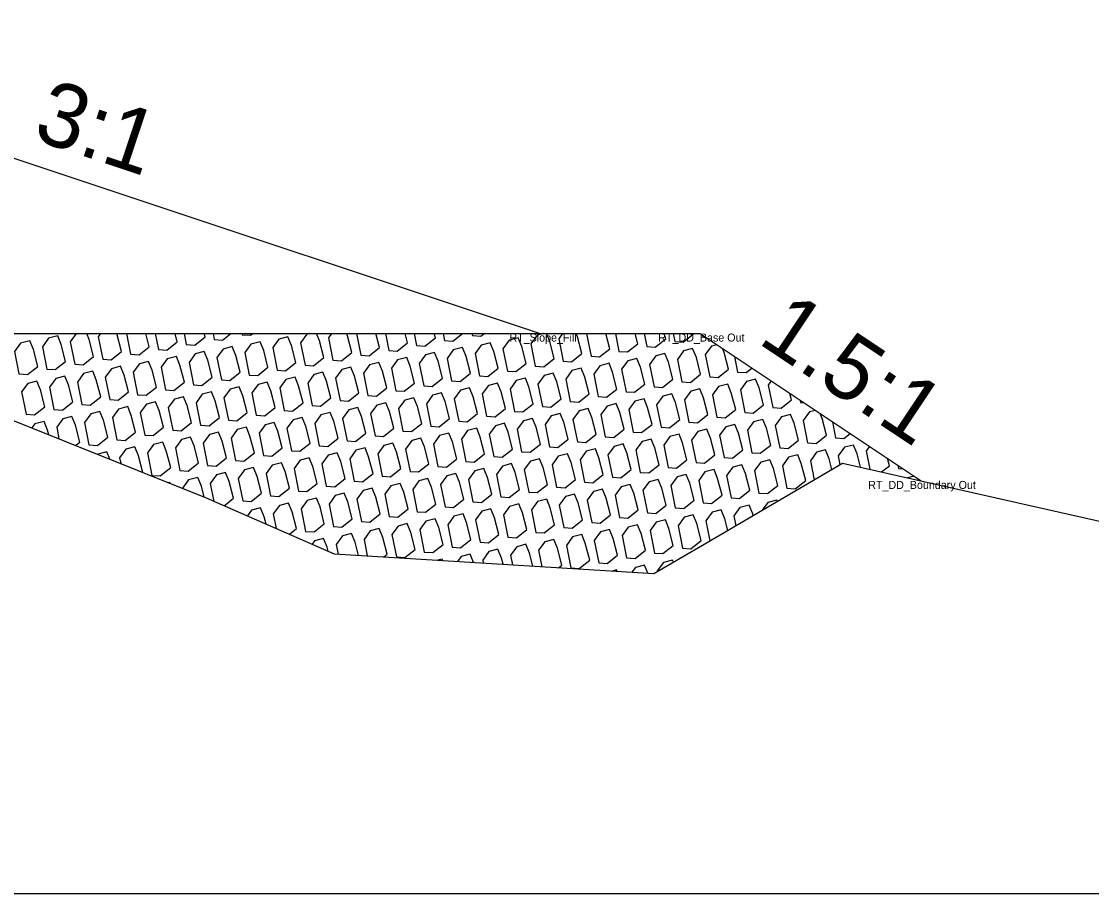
# Model space of a CAD drawing. Extents: x -26 to 203, y -10 to 20020.
# Drawn here: x 125.23 to 138.6, y 17000 to 17010.9 of the extents above; entities that cross this region are included whole.
import ezdxf

# ---------------------------------------------------------------- set-up
doc = ezdxf.new("R2010")
doc.units = 0
for name, color, linetype in [('Default', 7, 'Continuous'), ('Exist Cross Section Cell', 7, 'Continuous'), ('Exist XS Ground Line', 7, 'Continuous'), ('Old_Level_1', 7, 'Continuous'), ('Prop CMT Rip Rap Class II', 7, 'Continuous'), ('Prop CMT Slope Grass', 7, 'Continuous'), ('Prop XS Side Slope Text', 7, 'Continuous')]:
    doc.layers.add(name, color=color, linetype=linetype)

msp = doc.modelspace()

# ---------------------------------------------------------------- linework, layer by layer
at = {"layer": 'Exist Cross Section Cell'}
msp.add_line((100, 17000), (200, 17000), dxfattribs=at)
at = {"layer": 'Exist XS Ground Line'}
for p, q in [((124.169, 17006.298), (127.535, 17004.945)), ((133.788, 17004.385), (135.487, 17005.379)), ((135.487, 17005.379), (148.703, 17002.404)), ((127.535, 17004.945), (129.136, 17004.246)), ((133.13, 17004), (133.788, 17004.385)), ((129.136, 17004.246), (129.884, 17004.2)), ((129.884, 17004.2), (133.13, 17004))]:
    msp.add_line(p, q, dxfattribs=at)
at = {"layer": 'Old_Level_1'}
for p, q in [((126.538, 17007), (126.589, 17006.741)), ((126.899, 17007), (126.938, 17006.802)), ((127.259, 17007), (127.286, 17006.863)), ((127.62, 17007), (127.635, 17006.925)), ((127.981, 17007), (127.984, 17006.986)), ((129.413, 17007), (129.467, 17006.728)), ((129.774, 17007), (129.816, 17006.79)), ((130.135, 17007), (130.164, 17006.851)), ((130.495, 17007), (130.513, 17006.913)), ((130.856, 17007), (130.861, 17006.974)), ((132.649, 17007), (132.693, 17006.777)), ((133.01, 17007), (133.042, 17006.839)), ((133.371, 17007), (133.39, 17006.9)), ((133.735, 17006.981), (133.739, 17006.962)), ((133.739, 17006.962), (133.767, 17006.96)), ((134.138, 17006.712), (134.176, 17006.519)), ((134.957, 17006.166), (134.963, 17006.138)), ((134.963, 17006.138), (135.004, 17006.135)), ((135.36, 17005.898), (135.4, 17005.695)), ((136.179, 17005.352), (136.186, 17005.314)), ((136.186, 17005.314), (136.241, 17005.31)), ((136.379, 17005.218), (136.297, 17005.197)), ((136.435, 17005.166), (136.426, 17005.187))]:
    msp.add_line(p, q, dxfattribs=at)
for points in [[(125.543, 17006.556), (125.649, 17006.549), (125.778, 17006.652), (125.724, 17006.862), (125.679, 17006.972), (125.565, 17006.943), (125.488, 17006.836)], [(125.195, 17006.495), (125.3, 17006.487), (125.43, 17006.59), (125.375, 17006.801), (125.33, 17006.911), (125.216, 17006.881), (125.139, 17006.775)], [(133.131, 17006.335), (133.236, 17006.327), (133.365, 17006.43), (133.311, 17006.641), (133.266, 17006.751), (133.152, 17006.721), (133.075, 17006.615)], [(133.479, 17006.396), (133.585, 17006.389), (133.714, 17006.492), (133.66, 17006.702), (133.614, 17006.812), (133.501, 17006.783), (133.424, 17006.676)], [(129.207, 17006.163), (129.312, 17006.155), (129.442, 17006.258), (129.388, 17006.469), (129.342, 17006.579), (129.229, 17006.549), (129.152, 17006.443)], [(129.556, 17006.224), (129.661, 17006.217), (129.791, 17006.32), (129.736, 17006.53), (129.691, 17006.64), (129.577, 17006.611), (129.5, 17006.504)], [(132.433, 17006.212), (132.539, 17006.204), (132.668, 17006.307), (132.614, 17006.518), (132.569, 17006.628), (132.455, 17006.598), (132.378, 17006.492)], [(132.782, 17006.273), (132.887, 17006.266), (133.017, 17006.369), (132.962, 17006.579), (132.917, 17006.689), (132.804, 17006.66), (132.726, 17006.553)], [(128.51, 17006.04), (128.615, 17006.032), (128.745, 17006.135), (128.69, 17006.346), (128.645, 17006.456), (128.531, 17006.426), (128.454, 17006.32)], [(128.859, 17006.101), (128.964, 17006.094), (129.093, 17006.197), (129.039, 17006.407), (128.994, 17006.517), (128.88, 17006.488), (128.803, 17006.381)], [(132.085, 17006.15), (132.19, 17006.143), (132.32, 17006.246), (132.265, 17006.456), (132.22, 17006.566), (132.106, 17006.537), (132.029, 17006.43)], [(125.284, 17005.991), (125.389, 17005.983), (125.519, 17006.086), (125.464, 17006.297), (125.419, 17006.406), (125.305, 17006.377), (125.228, 17006.271)], [(127.813, 17005.917), (127.918, 17005.909), (128.048, 17006.012), (127.993, 17006.223), (127.948, 17006.333), (127.834, 17006.303), (127.757, 17006.197)], [(128.161, 17005.978), (128.267, 17005.971), (128.396, 17006.074), (128.342, 17006.284), (128.297, 17006.394), (128.183, 17006.365), (128.106, 17006.258)], [(130.69, 17005.904), (130.796, 17005.897), (130.925, 17006), (130.871, 17006.211), (130.826, 17006.32), (130.712, 17006.291), (130.635, 17006.184)], [(133.917, 17005.954), (134.022, 17005.946), (134.152, 17006.049), (134.097, 17006.26), (134.052, 17006.369), (133.938, 17006.34), (133.861, 17006.234)], [(127.116, 17005.794), (127.221, 17005.786), (127.35, 17005.889), (127.296, 17006.1), (127.251, 17006.21), (127.137, 17006.18), (127.06, 17006.074)], [(127.464, 17005.855), (127.57, 17005.848), (127.699, 17005.951), (127.645, 17006.161), (127.599, 17006.271), (127.486, 17006.242), (127.409, 17006.135)], [(130.342, 17005.843), (130.447, 17005.835), (130.577, 17005.939), (130.522, 17006.149), (130.477, 17006.259), (130.363, 17006.229), (130.286, 17006.123)], [(126.418, 17005.671), (126.524, 17005.663), (126.653, 17005.767), (126.599, 17005.977), (126.554, 17006.087), (126.44, 17006.057), (126.363, 17005.951)], [(126.767, 17005.732), (126.872, 17005.725), (127.002, 17005.828), (126.947, 17006.039), (126.902, 17006.148), (126.789, 17006.119), (126.711, 17006.012)], [(132.174, 17005.646), (132.279, 17005.639), (132.409, 17005.742), (132.354, 17005.952), (132.309, 17006.062), (132.195, 17006.033), (132.118, 17005.926)], [(128.599, 17005.536), (128.704, 17005.528), (128.834, 17005.631), (128.779, 17005.842), (128.734, 17005.952), (128.62, 17005.922), (128.543, 17005.816)], [(131.477, 17005.523), (131.582, 17005.516), (131.711, 17005.619), (131.657, 17005.829), (131.612, 17005.939), (131.498, 17005.91), (131.421, 17005.803)], [(131.825, 17005.585), (131.93, 17005.577), (132.06, 17005.68), (132.006, 17005.891), (131.96, 17006.001), (131.847, 17005.971), (131.77, 17005.865)], [(127.902, 17005.413), (128.007, 17005.405), (128.137, 17005.508), (128.082, 17005.719), (128.037, 17005.829), (127.923, 17005.799), (127.846, 17005.693)], [(128.25, 17005.474), (128.356, 17005.467), (128.485, 17005.57), (128.431, 17005.78), (128.386, 17005.89), (128.272, 17005.861), (128.195, 17005.754)], [(130.779, 17005.4), (130.885, 17005.393), (131.014, 17005.496), (130.96, 17005.707), (130.915, 17005.816), (130.801, 17005.787), (130.724, 17005.68)], [(131.128, 17005.462), (131.233, 17005.454), (131.363, 17005.557), (131.308, 17005.768), (131.263, 17005.878), (131.149, 17005.848), (131.072, 17005.742)], [(127.205, 17005.29), (127.31, 17005.282), (127.439, 17005.385), (127.385, 17005.596), (127.34, 17005.706), (127.226, 17005.676), (127.149, 17005.57)], [(127.553, 17005.351), (127.658, 17005.344), (127.788, 17005.447), (127.733, 17005.657), (127.688, 17005.767), (127.575, 17005.738), (127.498, 17005.631)], [(130.082, 17005.277), (130.187, 17005.27), (130.317, 17005.373), (130.263, 17005.584), (130.217, 17005.693), (130.104, 17005.664), (130.027, 17005.557)], [(130.431, 17005.339), (130.536, 17005.331), (130.666, 17005.435), (130.611, 17005.645), (130.566, 17005.755), (130.452, 17005.725), (130.375, 17005.619)], [(132.96, 17005.265), (133.065, 17005.258), (133.195, 17005.361), (133.14, 17005.571), (133.095, 17005.681), (132.981, 17005.652), (132.904, 17005.545)], [(133.308, 17005.327), (133.414, 17005.319), (133.543, 17005.422), (133.489, 17005.633), (133.444, 17005.742), (133.33, 17005.713), (133.253, 17005.607)], [(129.036, 17005.093), (129.142, 17005.085), (129.271, 17005.189), (129.217, 17005.399), (129.172, 17005.509), (129.058, 17005.48), (128.981, 17005.373)], [(129.385, 17005.155), (129.49, 17005.147), (129.62, 17005.25), (129.565, 17005.461), (129.52, 17005.57), (129.406, 17005.541), (129.329, 17005.435)], [(129.734, 17005.216), (129.839, 17005.208), (129.968, 17005.312), (129.914, 17005.522), (129.869, 17005.632), (129.755, 17005.602), (129.678, 17005.496)], [(132.263, 17005.142), (132.368, 17005.135), (132.497, 17005.238), (132.443, 17005.448), (132.398, 17005.558), (132.284, 17005.529), (132.207, 17005.422)], [(132.611, 17005.204), (132.717, 17005.196), (132.846, 17005.299), (132.792, 17005.51), (132.746, 17005.62), (132.633, 17005.59), (132.556, 17005.484)], [(128.688, 17005.032), (128.793, 17005.024), (128.923, 17005.127), (128.868, 17005.338), (128.823, 17005.447), (128.709, 17005.418), (128.632, 17005.312)], [(131.217, 17004.958), (131.322, 17004.95), (131.452, 17005.053), (131.397, 17005.264), (131.352, 17005.374), (131.238, 17005.344), (131.161, 17005.238)], [(131.565, 17005.019), (131.671, 17005.012), (131.8, 17005.115), (131.746, 17005.325), (131.701, 17005.435), (131.587, 17005.406), (131.51, 17005.299)], [(131.914, 17005.081), (132.019, 17005.073), (132.149, 17005.176), (132.094, 17005.387), (132.049, 17005.497), (131.935, 17005.467), (131.858, 17005.361)], [(134.443, 17005.007), (134.548, 17004.999), (134.678, 17005.103), (134.623, 17005.313), (134.578, 17005.423), (134.465, 17005.393), (134.387, 17005.287)], [(134.792, 17005.068), (134.897, 17005.061), (135.027, 17005.164), (134.972, 17005.375), (134.927, 17005.484), (134.813, 17005.455), (134.736, 17005.348)], [(130.52, 17004.835), (130.625, 17004.827), (130.754, 17004.93), (130.7, 17005.141), (130.655, 17005.251), (130.541, 17005.221), (130.464, 17005.115)], [(130.868, 17004.896), (130.974, 17004.889), (131.103, 17004.992), (131.049, 17005.202), (131.003, 17005.312), (130.89, 17005.283), (130.813, 17005.176)], [(133.397, 17004.823), (133.503, 17004.815), (133.632, 17004.918), (133.578, 17005.129), (133.533, 17005.238), (133.419, 17005.209), (133.342, 17005.103)], [(134.095, 17004.945), (134.2, 17004.938), (134.329, 17005.041), (134.275, 17005.252), (134.23, 17005.361), (134.116, 17005.332), (134.039, 17005.225)], [(129.822, 17004.712), (129.928, 17004.704), (130.057, 17004.808), (130.003, 17005.018), (129.958, 17005.128), (129.844, 17005.098), (129.767, 17004.992)], [(130.171, 17004.773), (130.276, 17004.766), (130.406, 17004.869), (130.351, 17005.08), (130.306, 17005.189), (130.193, 17005.16), (130.115, 17005.053)], [(132.7, 17004.7), (132.805, 17004.692), (132.935, 17004.795), (132.88, 17005.006), (132.835, 17005.115), (132.722, 17005.086), (132.645, 17004.98)], [(133.049, 17004.761), (133.154, 17004.753), (133.284, 17004.857), (133.229, 17005.067), (133.184, 17005.177), (133.07, 17005.148), (132.993, 17005.041)], [(129.474, 17004.65), (129.579, 17004.643), (129.709, 17004.746), (129.654, 17004.957), (129.609, 17005.066), (129.495, 17005.037), (129.418, 17004.93)], [(132.003, 17004.577), (132.108, 17004.569), (132.238, 17004.672), (132.183, 17004.883), (132.138, 17004.993), (132.024, 17004.963), (131.947, 17004.857)], [(132.352, 17004.638), (132.457, 17004.631), (132.586, 17004.734), (132.532, 17004.944), (132.487, 17005.054), (132.373, 17005.025), (132.296, 17004.918)], [(131.306, 17004.454), (131.411, 17004.446), (131.541, 17004.549), (131.486, 17004.76), (131.441, 17004.87), (131.327, 17004.84), (131.25, 17004.734)], [(131.654, 17004.515), (131.76, 17004.508), (131.889, 17004.611), (131.835, 17004.821), (131.79, 17004.931), (131.676, 17004.902), (131.599, 17004.795)], [(130.609, 17004.331), (130.714, 17004.323), (130.843, 17004.426), (130.789, 17004.637), (130.744, 17004.747), (130.63, 17004.717), (130.553, 17004.611)], [(130.957, 17004.392), (131.062, 17004.385), (131.192, 17004.488), (131.137, 17004.698), (131.092, 17004.808), (130.979, 17004.779), (130.902, 17004.672)], [(133.486, 17004.318), (133.591, 17004.311), (133.721, 17004.414), (133.667, 17004.625), (133.621, 17004.734), (133.508, 17004.705), (133.431, 17004.598)], [(130.26, 17004.269), (130.365, 17004.262), (130.495, 17004.365), (130.44, 17004.575), (130.395, 17004.685), (130.281, 17004.656), (130.204, 17004.549)], [(132.789, 17004.196), (132.894, 17004.188), (133.024, 17004.291), (132.969, 17004.502), (132.924, 17004.611), (132.81, 17004.582), (132.733, 17004.476)], [(133.138, 17004.257), (133.243, 17004.249), (133.372, 17004.353), (133.318, 17004.563), (133.273, 17004.673), (133.159, 17004.643), (133.082, 17004.537)], [(132.092, 17004.073), (132.197, 17004.065), (132.327, 17004.168), (132.272, 17004.379), (132.227, 17004.488), (132.113, 17004.459), (132.036, 17004.353)], [(132.44, 17004.134), (132.546, 17004.126), (132.675, 17004.23), (132.621, 17004.44), (132.576, 17004.55), (132.462, 17004.521), (132.385, 17004.414)]]:
    msp.add_lwpolyline(points, close=True, dxfattribs=at)
for points in [[(125.911, 17007), (125.836, 17006.898), (125.892, 17006.618)], [(125.892, 17006.618), (125.997, 17006.61), (126.127, 17006.713), (126.072, 17006.924), (126.041, 17007)], [(126.215, 17007), (126.185, 17006.959), (126.241, 17006.679)], [(126.241, 17006.679), (126.346, 17006.671), (126.475, 17006.775), (126.421, 17006.985), (126.415, 17007)], [(126.589, 17006.741), (126.695, 17006.733), (126.824, 17006.836), (126.782, 17007)], [(126.938, 17006.802), (127.043, 17006.794), (127.173, 17006.898), (127.146, 17007)], [(127.286, 17006.863), (127.392, 17006.856), (127.521, 17006.959), (127.511, 17007)], [(127.635, 17006.925), (127.74, 17006.917), (127.844, 17007)], [(127.984, 17006.986), (128.089, 17006.979), (128.116, 17007)], [(128.823, 17007), (128.791, 17006.992), (128.714, 17006.885), (128.77, 17006.605)], [(128.77, 17006.605), (128.875, 17006.598), (129.005, 17006.701), (128.95, 17006.911), (128.914, 17007)], [(129.101, 17007), (129.063, 17006.947), (129.118, 17006.667)], [(129.118, 17006.667), (129.224, 17006.659), (129.353, 17006.762), (129.299, 17006.973), (129.288, 17007)], [(129.467, 17006.728), (129.572, 17006.721), (129.702, 17006.824), (129.656, 17007)], [(129.816, 17006.79), (129.921, 17006.782), (130.05, 17006.885), (130.021, 17007)], [(130.164, 17006.851), (130.269, 17006.844), (130.399, 17006.947), (130.385, 17007)], [(130.513, 17006.913), (130.618, 17006.905), (130.737, 17007)], [(130.861, 17006.974), (130.967, 17006.966), (131.009, 17007)], [(131.749, 17007), (131.669, 17006.979), (131.592, 17006.873), (131.647, 17006.593)], [(131.647, 17006.593), (131.753, 17006.585), (131.882, 17006.689), (131.828, 17006.899), (131.786, 17007)], [(131.988, 17007), (131.94, 17006.934), (131.996, 17006.654)], [(131.996, 17006.654), (132.101, 17006.647), (132.231, 17006.75), (132.176, 17006.961), (132.16, 17007)], [(132.292, 17007), (132.289, 17006.996), (132.345, 17006.716)], [(132.345, 17006.716), (132.45, 17006.708), (132.579, 17006.811), (132.531, 17007)], [(132.693, 17006.777), (132.798, 17006.77), (132.928, 17006.873), (132.895, 17007)], [(133.042, 17006.839), (133.147, 17006.831), (133.277, 17006.934), (133.26, 17007)], [(133.39, 17006.9), (133.496, 17006.893), (133.625, 17006.996), (133.624, 17007)], [(128.073, 17006.482), (128.178, 17006.475), (128.307, 17006.578), (128.253, 17006.788), (128.208, 17006.898), (128.094, 17006.869), (128.017, 17006.762), (128.073, 17006.482)], [(128.421, 17006.544), (128.526, 17006.536), (128.656, 17006.639), (128.602, 17006.85), (128.556, 17006.96), (128.443, 17006.93), (128.366, 17006.824), (128.421, 17006.544)], [(130.95, 17006.47), (131.055, 17006.462), (131.185, 17006.566), (131.131, 17006.776), (131.085, 17006.886), (130.972, 17006.856), (130.895, 17006.75), (130.95, 17006.47)], [(131.299, 17006.531), (131.404, 17006.524), (131.534, 17006.627), (131.479, 17006.838), (131.434, 17006.947), (131.32, 17006.918), (131.243, 17006.811), (131.299, 17006.531)], [(133.915, 17006.861), (133.849, 17006.844), (133.772, 17006.738), (133.828, 17006.458)], [(127.027, 17006.298), (127.132, 17006.29), (127.262, 17006.394), (127.207, 17006.604), (127.162, 17006.714), (127.048, 17006.684), (126.971, 17006.578), (127.027, 17006.298)], [(127.375, 17006.359), (127.481, 17006.352), (127.61, 17006.455), (127.556, 17006.666), (127.511, 17006.775), (127.397, 17006.746), (127.32, 17006.639), (127.375, 17006.359)], [(127.724, 17006.421), (127.829, 17006.413), (127.959, 17006.516), (127.904, 17006.727), (127.859, 17006.837), (127.745, 17006.807), (127.668, 17006.701), (127.724, 17006.421)], [(130.253, 17006.347), (130.358, 17006.339), (130.488, 17006.443), (130.433, 17006.653), (130.388, 17006.763), (130.274, 17006.734), (130.197, 17006.627), (130.253, 17006.347)], [(130.602, 17006.409), (130.707, 17006.401), (130.836, 17006.504), (130.782, 17006.715), (130.737, 17006.824), (130.623, 17006.795), (130.546, 17006.689), (130.602, 17006.409)], [(133.828, 17006.458), (133.933, 17006.45), (134.063, 17006.553), (134.008, 17006.764), (133.988, 17006.812)], [(126.33, 17006.175), (126.435, 17006.167), (126.564, 17006.271), (126.51, 17006.481), (126.465, 17006.591), (126.351, 17006.561), (126.274, 17006.455), (126.33, 17006.175)], [(126.678, 17006.236), (126.783, 17006.229), (126.913, 17006.332), (126.859, 17006.543), (126.813, 17006.652), (126.7, 17006.623), (126.623, 17006.516), (126.678, 17006.236)], [(129.904, 17006.286), (130.01, 17006.278), (130.139, 17006.381), (130.085, 17006.592), (130.04, 17006.701), (129.926, 17006.672), (129.849, 17006.566), (129.904, 17006.286)], [(125.632, 17006.052), (125.738, 17006.044), (125.867, 17006.148), (125.813, 17006.358), (125.768, 17006.468), (125.654, 17006.439), (125.577, 17006.332), (125.632, 17006.052)], [(125.981, 17006.114), (126.086, 17006.106), (126.216, 17006.209), (126.161, 17006.42), (126.116, 17006.529), (126.002, 17006.5), (125.925, 17006.394), (125.981, 17006.114)], [(131.388, 17006.027), (131.493, 17006.02), (131.622, 17006.123), (131.568, 17006.334), (131.523, 17006.443), (131.409, 17006.414), (131.332, 17006.307), (131.388, 17006.027)], [(131.736, 17006.089), (131.842, 17006.081), (131.971, 17006.184), (131.917, 17006.395), (131.871, 17006.505), (131.758, 17006.475), (131.681, 17006.369), (131.736, 17006.089)], [(134.176, 17006.519), (134.282, 17006.512), (134.354, 17006.569)], [(131.039, 17005.966), (131.144, 17005.958), (131.274, 17006.062), (131.219, 17006.272), (131.174, 17006.382), (131.061, 17006.352), (130.983, 17006.246), (131.039, 17005.966)], [(133.568, 17005.892), (133.673, 17005.885), (133.803, 17005.988), (133.749, 17006.198), (133.703, 17006.308), (133.59, 17006.279), (133.513, 17006.172), (133.568, 17005.892)], [(134.265, 17006.015), (134.371, 17006.007), (134.5, 17006.111), (134.446, 17006.321), (134.401, 17006.431), (134.287, 17006.402), (134.21, 17006.295), (134.265, 17006.015)], [(134.595, 17006.408), (134.558, 17006.357), (134.614, 17006.077)], [(129.993, 17005.782), (130.099, 17005.774), (130.228, 17005.877), (130.174, 17006.088), (130.129, 17006.197), (130.015, 17006.168), (129.938, 17006.062), (129.993, 17005.782)], [(132.871, 17005.769), (132.976, 17005.762), (133.106, 17005.865), (133.051, 17006.075), (133.006, 17006.185), (132.892, 17006.156), (132.815, 17006.049), (132.871, 17005.769)], [(133.22, 17005.831), (133.325, 17005.823), (133.454, 17005.926), (133.4, 17006.137), (133.355, 17006.247), (133.241, 17006.217), (133.164, 17006.111), (133.22, 17005.831)], [(134.614, 17006.077), (134.719, 17006.069), (134.849, 17006.172), (134.828, 17006.252)], [(129.296, 17005.659), (129.401, 17005.651), (129.531, 17005.754), (129.476, 17005.965), (129.431, 17006.074), (129.318, 17006.045), (129.24, 17005.939), (129.296, 17005.659)], [(129.645, 17005.72), (129.75, 17005.712), (129.88, 17005.816), (129.825, 17006.026), (129.78, 17006.136), (129.666, 17006.107), (129.589, 17006), (129.645, 17005.72)], [(132.522, 17005.708), (132.628, 17005.7), (132.757, 17005.803), (132.703, 17006.014), (132.658, 17006.124), (132.544, 17006.094), (132.467, 17005.988), (132.522, 17005.708)], [(135.147, 17006.04), (135.073, 17006.02), (134.996, 17005.914), (135.051, 17005.634)], [(125.568, 17005.736), (125.553, 17005.793), (125.508, 17005.902), (125.394, 17005.873), (125.357, 17005.821)], [(125.903, 17005.601), (125.956, 17005.644), (125.902, 17005.854), (125.856, 17005.964), (125.743, 17005.934), (125.666, 17005.828), (125.694, 17005.685)], [(126.07, 17005.609), (126.175, 17005.602), (126.305, 17005.705), (126.25, 17005.916), (126.205, 17006.025), (126.091, 17005.996), (126.014, 17005.889), (126.07, 17005.609)], [(128.948, 17005.597), (129.053, 17005.59), (129.182, 17005.693), (129.128, 17005.903), (129.083, 17006.013), (128.969, 17005.984), (128.892, 17005.877), (128.948, 17005.597)], [(134.354, 17005.511), (134.459, 17005.503), (134.589, 17005.607), (134.535, 17005.817), (134.489, 17005.927), (134.376, 17005.897), (134.299, 17005.791), (134.354, 17005.511)], [(134.703, 17005.572), (134.808, 17005.565), (134.938, 17005.668), (134.883, 17005.879), (134.838, 17005.988), (134.724, 17005.959), (134.647, 17005.852), (134.703, 17005.572)], [(135.051, 17005.634), (135.157, 17005.626), (135.286, 17005.73), (135.232, 17005.94), (135.207, 17006)], [(133.657, 17005.388), (133.762, 17005.38), (133.892, 17005.484), (133.837, 17005.694), (133.792, 17005.804), (133.678, 17005.775), (133.601, 17005.668), (133.657, 17005.388)], [(134.006, 17005.45), (134.111, 17005.442), (134.24, 17005.545), (134.186, 17005.756), (134.141, 17005.865), (134.027, 17005.836), (133.95, 17005.73), (134.006, 17005.45)], [(126.856, 17005.228), (126.961, 17005.221), (127.091, 17005.324), (127.036, 17005.534), (126.991, 17005.644), (126.877, 17005.615), (126.8, 17005.508), (126.856, 17005.228)], [(135.4, 17005.695), (135.505, 17005.688), (135.583, 17005.749)], [(126.332, 17005.429), (126.294, 17005.521), (126.18, 17005.492), (126.179, 17005.49)], [(126.742, 17005.264), (126.688, 17005.473), (126.643, 17005.583), (126.529, 17005.553), (126.452, 17005.447), (126.466, 17005.375)], [(135.355, 17005.302), (135.321, 17005.436), (135.276, 17005.546), (135.162, 17005.516), (135.085, 17005.41), (135.132, 17005.172)], [(135.713, 17005.328), (135.669, 17005.497), (135.624, 17005.607), (135.51, 17005.578), (135.433, 17005.471), (135.455, 17005.361)], [(135.823, 17005.589), (135.782, 17005.533), (135.828, 17005.303)], [(128.339, 17004.97), (128.444, 17004.963), (128.574, 17005.066), (128.52, 17005.276), (128.474, 17005.386), (128.361, 17005.357), (128.284, 17005.25), (128.339, 17004.97)], [(135.974, 17005.27), (136.072, 17005.348), (136.049, 17005.438)], [(127.758, 17004.848), (127.877, 17004.943), (127.822, 17005.153), (127.777, 17005.263), (127.663, 17005.234), (127.586, 17005.127), (127.631, 17004.903)], [(127.991, 17004.909), (128.096, 17004.901), (128.225, 17005.004), (128.171, 17005.215), (128.126, 17005.325), (128.012, 17005.295), (127.935, 17005.189), (127.991, 17004.909)], [(133.746, 17004.884), (133.851, 17004.876), (133.981, 17004.98), (133.926, 17005.19), (133.881, 17005.3), (133.767, 17005.27), (133.69, 17005.164), (133.746, 17004.884)], [(127.086, 17005.126), (127.08, 17005.14), (127.062, 17005.135)], [(127.509, 17004.956), (127.474, 17005.092), (127.429, 17005.202), (127.315, 17005.172), (127.238, 17005.066), (127.238, 17005.065)], [(129.125, 17004.589), (129.231, 17004.581), (129.36, 17004.685), (129.306, 17004.895), (129.26, 17005.005), (129.147, 17004.975), (129.07, 17004.869), (129.125, 17004.589)], [(128.575, 17004.491), (128.663, 17004.562), (128.608, 17004.772), (128.563, 17004.882), (128.45, 17004.853), (128.372, 17004.746), (128.409, 17004.564)], [(128.777, 17004.528), (128.882, 17004.52), (129.011, 17004.623), (128.957, 17004.834), (128.912, 17004.943), (128.798, 17004.914), (128.721, 17004.808), (128.777, 17004.528)], [(134.369, 17004.725), (134.364, 17004.748), (134.319, 17004.857), (134.205, 17004.828), (134.128, 17004.721), (134.152, 17004.598)], [(134.674, 17004.903), (134.667, 17004.919), (134.553, 17004.889), (134.483, 17004.792)], [(128.284, 17004.618), (128.26, 17004.711), (128.215, 17004.82), (128.101, 17004.791), (128.05, 17004.72)], [(134.053, 17004.54), (134.015, 17004.686), (133.97, 17004.796), (133.856, 17004.766), (133.779, 17004.66), (133.829, 17004.409)], [(129.911, 17004.208), (130.017, 17004.2), (130.146, 17004.303), (130.092, 17004.514), (130.047, 17004.624), (129.933, 17004.594), (129.856, 17004.488), (129.911, 17004.208)], [(129.059, 17004.28), (129.046, 17004.33), (129.001, 17004.439), (128.887, 17004.41), (128.857, 17004.368)], [(129.437, 17004.228), (129.395, 17004.391), (129.349, 17004.501), (129.236, 17004.471), (129.159, 17004.365), (129.183, 17004.243)], [(129.755, 17004.208), (129.798, 17004.242), (129.743, 17004.453), (129.698, 17004.562), (129.584, 17004.533), (129.507, 17004.426), (129.548, 17004.221)], [(131.247, 17004.116), (131.226, 17004.194), (131.181, 17004.304), (131.067, 17004.275), (130.99, 17004.168), (130.998, 17004.131)], [(131.617, 17004.093), (131.575, 17004.256), (131.53, 17004.366), (131.416, 17004.336), (131.339, 17004.23), (131.363, 17004.109)], [(131.936, 17004.073), (131.978, 17004.107), (131.924, 17004.317), (131.878, 17004.427), (131.765, 17004.398), (131.688, 17004.291), (131.728, 17004.086)], [(130.492, 17004.163), (130.484, 17004.181), (130.428, 17004.167)], [(130.875, 17004.139), (130.833, 17004.243), (130.719, 17004.213), (130.674, 17004.151)], [(133.373, 17004.142), (133.362, 17004.169), (133.248, 17004.139), (133.171, 17004.033), (133.172, 17004.025)], [(132.672, 17004.028), (132.664, 17004.046), (132.61, 17004.032)], [(133.055, 17004.004), (133.013, 17004.107), (132.899, 17004.078), (132.855, 17004.017)]]:
    msp.add_lwpolyline(points, dxfattribs=at)
at = {"layer": 'Prop CMT Rip Rap Class II'}
msp.add_lwpolyline([(122.104, 17007), (133.707, 17007), (136.469, 17005.158)], dxfattribs=at)
at = {"layer": 'Prop CMT Slope Grass'}
msp.add_lwpolyline([(120, 17010.902), (131.707, 17007)], dxfattribs=at)

# ---------------------------------------------------------------- texts
at = {"layer": 'Default'}
for s, p in [('RT_Slope_Fill', (131.324, 17006.9)), ('RT_DD_Base Out', (133.184, 17006.9)), ('RT_DD_Boundary Out', (135.808, 17005.058))]:
    msp.add_text(s, height=0.1, dxfattribs=at).set_placement(p)
at = {"layer": 'Prop XS Side Slope Text'}
for s, rotation, p in [('3:1', 341.5668, (125.347, 17009.436)), ('1.5:1', 326.3086, (134.412, 17006.891))]:
    msp.add_text(s, height=0.8, rotation=rotation, dxfattribs=at).set_placement(p)

doc.saveas('drawing.dxf')
